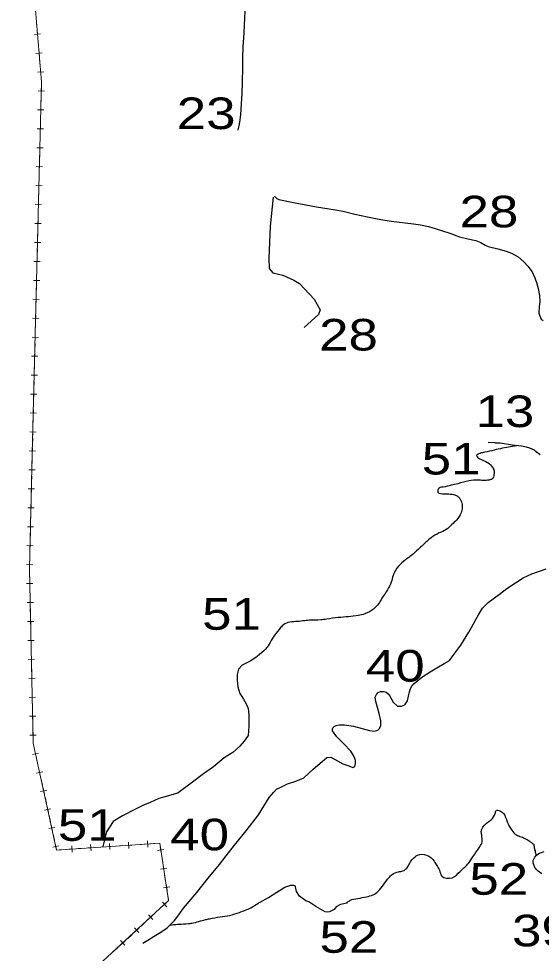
# Model space of a CAD drawing. Extents: x 476989 to 498418, y 4381813 to 4416555.
# Drawn here: x 483851 to 484677, y 4385658 to 4387137 of the extents above; entities that cross this region are included whole.
import ezdxf
from ezdxf.enums import TextEntityAlignment as Align

# ---------------------------------------------------------------- set-up
doc = ezdxf.new("R2010")
doc.units = 0
doc.header["$LTSCALE"] = 20
for name, color, linetype, lineweight in [('13', 7, 'Continuous', 13), ('34', 7, 'Continuous', 13), ('6', 7, 'Continuous', 25)]:
    doc.layers.add(name, color=color, linetype=linetype, lineweight=lineweight)

msp = doc.modelspace()

# ---------------------------------------------------------------- linework, layer by layer
at = {"layer": '34'}
for p, q in [((483879.05, 4387132.21), (483879.88, 4387122.24)), ((483875.73, 4387111.86), (483885.7, 4387112.69)), ((483880.3, 4387117.26), (483881.13, 4387107.29)), ((483881.54, 4387102.31), (483882.38, 4387092.35)), ((483878.23, 4387081.96), (483888.19, 4387082.8)), ((483882.79, 4387087.36), (483883.63, 4387077.4)), ((483884.04, 4387072.41), (483884.87, 4387062.45)), ((483880.72, 4387052.07), (483890.69, 4387052.9)), ((483885.29, 4387057.47), (483886.12, 4387047.5)), ((483881.65, 4387022.67), (483891.64, 4387022.42)), ((483886.77, 4387027.54), (483886.52, 4387017.54)), ((483886.4, 4387012.55), (483886.15, 4387002.55)), ((483880.91, 4386992.67), (483890.9, 4386992.43)), ((483886.03, 4386997.55), (483885.78, 4386987.55)), ((483885.66, 4386982.55), (483885.41, 4386972.56)), ((483880.17, 4386962.68), (483890.16, 4386962.44)), ((483885.29, 4386967.56), (483885.04, 4386957.56)), ((483884.92, 4386952.56), (483884.67, 4386942.57)), ((483879.43, 4386932.69), (483889.42, 4386932.45)), ((483884.55, 4386937.57), (483884.3, 4386927.57)), ((483884.18, 4386922.57), (483883.93, 4386912.58)), ((483878.69, 4386902.7), (483888.69, 4386902.46)), ((483883.81, 4386907.58), (483883.56, 4386897.58)), ((483883.44, 4386892.58), (483883.19, 4386882.58)), ((483877.95, 4386872.71), (483887.95, 4386872.46)), ((483883.07, 4386877.59), (483882.83, 4386867.59)), ((483882.7, 4386862.59), (483882.46, 4386852.59)), ((483877.21, 4386842.72), (483887.21, 4386842.47)), ((483882.33, 4386847.6), (483882.09, 4386837.6)), ((483881.96, 4386832.6), (483881.72, 4386822.6)), ((483876.47, 4386812.73), (483886.47, 4386812.48)), ((483881.59, 4386817.6), (483881.35, 4386807.61)), ((483881.22, 4386802.61), (483880.98, 4386792.61)), ((483875.73, 4386782.74), (483885.73, 4386782.49)), ((483880.85, 4386787.61), (483880.61, 4386777.62)), ((483880.48, 4386772.62), (483880.24, 4386762.62)), ((483874.99, 4386752.75), (483884.99, 4386752.5)), ((483880.12, 4386757.62), (483879.87, 4386747.63)), ((483879.75, 4386742.63), (483879.5, 4386732.63)), ((483874.25, 4386722.76), (483884.25, 4386722.51)), ((483879.38, 4386727.63), (483879.13, 4386717.64)), ((483879.01, 4386712.64), (483878.76, 4386702.64)), ((483878.64, 4386697.64), (483878.39, 4386687.64)), ((483873.52, 4386692.77), (483883.51, 4386692.52)), ((483878.27, 4386682.65), (483878.02, 4386672.65)), ((483877.9, 4386667.65), (483877.65, 4386657.65)), ((483872.78, 4386662.77), (483882.77, 4386662.53)), ((483877.53, 4386652.65), (483877.28, 4386642.66)), ((483877.16, 4386637.66), (483876.91, 4386627.66)), ((483872.04, 4386632.78), (483882.03, 4386632.54)), ((483876.79, 4386622.66), (483876.54, 4386612.67)), ((483876.42, 4386607.67), (483876.17, 4386597.67)), ((483871.3, 4386602.79), (483881.3, 4386602.55)), ((483876.05, 4386592.67), (483875.8, 4386582.68)), ((483875.68, 4386577.68), (483875.43, 4386567.68)), ((483870.56, 4386572.8), (483880.56, 4386572.56)), ((483875.31, 4386562.68), (483875.06, 4386552.69)), ((483874.94, 4386547.69), (483874.7, 4386537.69)), ((483869.82, 4386542.81), (483879.82, 4386542.56)), ((483874.57, 4386532.69), (483874.33, 4386522.69)), ((483874.2, 4386517.7), (483873.96, 4386507.7)), ((483869.08, 4386512.82), (483879.08, 4386512.57)), ((483873.83, 4386502.7), (483873.59, 4386492.7)), ((483873.46, 4386487.7), (483873.22, 4386477.71)), ((483868.34, 4386482.83), (483878.34, 4386482.58)), ((483873.09, 4386472.71), (483872.85, 4386462.71)), ((483872.72, 4386457.71), (483872.5, 4386448.65)), ((483867.6, 4386452.84), (483877.6, 4386452.59)), ((483872.35, 4386442.72), (483872.11, 4386432.72)), ((483872.5, 4386448.65), (483872.48, 4386447.72)), ((483871.99, 4386427.72), (483871.74, 4386417.73)), ((483866.86, 4386422.85), (483876.86, 4386422.6)), ((483871.62, 4386412.73), (483871.37, 4386402.73)), ((483871.25, 4386397.73), (483871, 4386387.74)), ((483866.12, 4386392.86), (483876.12, 4386392.61)), ((483870.88, 4386382.74), (483870.63, 4386372.74)), ((483870.51, 4386367.74), (483870.26, 4386357.74)), ((483865.39, 4386362.87), (483875.38, 4386362.62)), ((483870.14, 4386352.75), (483869.89, 4386342.75)), ((483864.65, 4386332.88), (483874.64, 4386332.63)), ((483869.77, 4386337.75), (483869.52, 4386327.75)), ((483869.4, 4386322.75), (483869.15, 4386312.76)), ((483863.91, 4386302.88), (483873.9, 4386302.64)), ((483869.03, 4386307.76), (483868.78, 4386297.76)), ((483868.66, 4386292.76), (483868.41, 4386282.77)), ((483863.17, 4386272.89), (483873.17, 4386272.65)), ((483868.29, 4386277.77), (483868.04, 4386267.77)), ((483868.07, 4386262.77), (483868.29, 4386252.78)), ((483863.51, 4386242.67), (483873.5, 4386242.89)), ((483868.4, 4386247.78), (483868.61, 4386237.78)), ((483868.72, 4386232.78), (483868.94, 4386222.78)), ((483864.16, 4386212.68), (483874.16, 4386212.89)), ((483869.05, 4386217.78), (483869.27, 4386207.79)), ((483869.37, 4386202.79), (483869.59, 4386192.79)), ((483864.81, 4386182.68), (483874.81, 4386182.9)), ((483869.7, 4386187.79), (483869.92, 4386177.79)), ((483870.03, 4386172.79), (483870.24, 4386162.8)), ((483865.46, 4386152.69), (483875.46, 4386152.91)), ((483870.35, 4386157.8), (483870.57, 4386147.8)), ((483870.68, 4386142.8), (483870.9, 4386132.8)), ((483866.11, 4386122.7), (483876.11, 4386122.91)), ((483871, 4386127.8), (483871.22, 4386117.81)), ((483871.33, 4386112.81), (483871.55, 4386102.81)), ((483866.77, 4386092.7), (483876.76, 4386092.92)), ((483871.66, 4386097.81), (483871.87, 4386087.81)), ((483871.98, 4386082.82), (483872.2, 4386072.82)), ((483867.42, 4386062.71), (483877.42, 4386062.93)), ((483872.31, 4386067.82), (483872.53, 4386057.82)), ((483872.63, 4386052.82), (483872.85, 4386042.82)), ((483868.07, 4386032.72), (483878.07, 4386032.94)), ((483872.96, 4386037.83), (483873.18, 4386027.83)), ((483873.29, 4386022.83), (483873.5, 4386012.83)), ((483868.72, 4386002.73), (483878.72, 4386002.94)), ((483873.61, 4386007.83), (483873.83, 4385997.84)), ((483872.79, 4385972.17), (483882.55, 4385974.3)), ((483876.6, 4385978.12), (483878.74, 4385968.35)), ((483879.81, 4385963.47), (483881.95, 4385953.7)), ((483879.2, 4385942.86), (483888.97, 4385945)), ((483883.02, 4385948.81), (483885.16, 4385939.04)), ((483886.23, 4385934.16), (483888.36, 4385924.39)), ((483885.62, 4385913.55), (483895.39, 4385915.69)), ((483889.43, 4385919.51), (483891.57, 4385909.74)), ((483892.64, 4385904.85), (483894.78, 4385895.09)), ((483892.03, 4385884.25), (483901.8, 4385886.39)), ((483895.85, 4385890.2), (483897.99, 4385880.43)), ((483899.06, 4385875.55), (483901.2, 4385865.78)), ((483898.45, 4385854.94), (483908.22, 4385857.08)), ((483902.27, 4385860.9), (483904.4, 4385851.13)), ((483905.47, 4385846.24), (483907.61, 4385836.47)), ((484055.17, 4385825.72), (484054.5, 4385835.7)), ((483904.87, 4385825.64), (483914.64, 4385827.77)), ((483908.68, 4385831.59), (483910.82, 4385821.82)), ((483915.15, 4385821.28), (483925.13, 4385821.95)), ((483930.12, 4385822.29), (483940.09, 4385822.96)), ((483935.44, 4385817.64), (483934.77, 4385827.62)), ((483945.08, 4385823.3), (483955.06, 4385823.97)), ((483960.05, 4385824.31), (483970.03, 4385824.98)), ((483965.37, 4385819.66), (483964.7, 4385829.64)), ((483975.01, 4385825.32), (483984.99, 4385825.99)), ((483989.98, 4385826.33), (483999.96, 4385827)), ((483995.31, 4385821.68), (483994.63, 4385831.66)), ((484004.95, 4385827.34), (484014.92, 4385828.01)), ((484019.91, 4385828.35), (484029.89, 4385829.02)), ((484025.24, 4385823.7), (484024.56, 4385833.68)), ((484034.88, 4385829.36), (484044.86, 4385830.03)), ((484049.84, 4385830.37), (484059.82, 4385831.04)), ((484070.7, 4385820.58), (484080.58, 4385822.1)), ((484074.88, 4385826.28), (484076.4, 4385816.39)), ((484077.16, 4385811.45), (484078.68, 4385801.57)), ((484075.26, 4385790.93), (484085.14, 4385792.45)), ((484079.44, 4385796.63), (484080.96, 4385786.74)), ((484081.72, 4385781.8), (484083.24, 4385771.92)), ((484079.82, 4385761.27), (484089.71, 4385762.79)), ((484084, 4385766.98), (484085.52, 4385757.09)), ((484086.28, 4385752.15), (484087.81, 4385742.27)), ((484085.27, 4385738.48), (484077.93, 4385731.69)), ((484078.2, 4385738.75), (484084.99, 4385731.41)), ((484063.24, 4385718.11), (484055.9, 4385711.32)), ((484056.18, 4385718.38), (484062.97, 4385711.04)), ((484074.26, 4385728.29), (484066.92, 4385721.5)), ((484052.23, 4385707.92), (484044.89, 4385701.13)), ((484030.21, 4385687.56), (484022.86, 4385680.77)), ((484041.22, 4385697.74), (484033.88, 4385690.95)), ((484034.15, 4385698.02), (484040.94, 4385690.67)), ((484019.19, 4385677.37), (484011.85, 4385670.58)), ((484012.13, 4385677.65), (484018.92, 4385670.31)), ((484008.18, 4385667.19), (484000.84, 4385660.4))]:
    msp.add_line(p, q, dxfattribs=at)
for points in [[(484108, 4387807), (483853, 4387811), (483851, 4387468), (483887, 4387037), (483872.5, 4386448.65)], [(483886.54, 4387042.52), (483887, 4387037), (483886.89, 4387032.54)], [(483872.5, 4386448.65), (483868, 4386266), (483874, 4385990), (483911, 4385821), (484074, 4385832), (484088, 4385741), (483902, 4385569), (484007, 4385465), (484103, 4385395), (484103.22, 4385394.84)], [(483873.94, 4385992.84), (483874, 4385990), (483875.53, 4385983)], [(484064.81, 4385831.38), (484074, 4385832), (484074.12, 4385831.22)]]:
    msp.add_lwpolyline(points, dxfattribs=at)
at = {"layer": '6'}
msp.add_line((484669.78, 4386451.55), (484675.59, 4386447), dxfattribs=at)
for points in [[(484212.82, 4387295.28), (484212.47, 4387278.4), (484211.44, 4387240.58), (484210.65, 4387220.54), (484209.3, 4387209.89), (484208.08, 4387198.84), (484207.98, 4387189.84), (484208.12, 4387179.31), (484208.42, 4387167.67), (484208.7, 4387158.03), (484208.44, 4387149.25), (484207.87, 4387137.58), (484207.04, 4387114.72), (484205.45, 4387091.7), (484204.57, 4387075.39), (484204.95, 4387059.47), (484204.36, 4387036.27), (484203.86, 4387018.17), (484202.77, 4387002.21), (484201.65, 4386984.79), (484200.05, 4386972.86), (484199.05, 4386967.22), (484197.58, 4386960.92), (484197.42, 4386960.48)], [(484255.26, 4386856.24), (484255.51, 4386855.85), (484259.2, 4386852.12), (484262.08, 4386850.81), (484285.37, 4386846.1), (484321.78, 4386839.14), (484351.99, 4386834.18), (484364.12, 4386832.42), (484382.29, 4386827.59), (484402.33, 4386823.45), (484423.29, 4386819.3), (484439.77, 4386816.4), (484475.05, 4386811.94), (484486.31, 4386810.65), (484498.67, 4386808.05), (484509.39, 4386804.9), (484532.44, 4386797.25), (484547.84, 4386791.37), (484560.89, 4386788.41), (484573.56, 4386785.73), (484581.82, 4386782.58), (484588.73, 4386778.34), (484593.26, 4386776.54), (484608.53, 4386772.83), (484621.89, 4386768.75), (484629.95, 4386765.83), (484640.85, 4386759.96), (484649.61, 4386752.18), (484656.1, 4386745.44), (484662.74, 4386736.14), (484667.21, 4386726.6), (484670.12, 4386717.75), (484672.45, 4386709.7), (484674.51, 4386698.8), (484674.86, 4386688.69), (484673.94, 4386681.56), (484673.61, 4386671.01), (484674.2, 4386667.61), (484677.03, 4386661.52), (484680.13, 4386659.31)], [(484253.58, 4386854.18), (484248.8, 4386808.66), (484246.41, 4386757.54), (484247.21, 4386741.57), (484252.78, 4386734.38), (484268.71, 4386731.19), (484286.22, 4386723.2), (484294.98, 4386717.61), (484318.07, 4386692.85), (484327.62, 4386676.08), (484325.23, 4386668.89), (484302.14, 4386648.12)], [(484593.43, 4386466.83), (484593.45, 4386466.82), (484603.22, 4386466), (484604.19, 4386465.78), (484612, 4386465.4), (484631.54, 4386462.29), (484646.09, 4386460.77), (484653.53, 4386459.28), (484658.44, 4386457.47), (484658.41, 4386457.42), (484665.79, 4386454.57), (484669.78, 4386451.55)], [(484379.37, 4385951.8), (484382.66, 4385953.41), (484383.69, 4385958.07), (484383.38, 4385962.64), (484382.38, 4385966.13), (484380.36, 4385970.61), (484376.08, 4385977.48), (484365.25, 4385989.07), (484353.82, 4386000.13), (484347.19, 4386009.82), (484347.05, 4386012.71), (484347.75, 4386014.63), (484350.02, 4386016.52), (484352.81, 4386018.1), (484357.54, 4386019.26), (484364.31, 4386019.32), (484365.47, 4386019.23), (484380.1, 4386017.06), (484394.06, 4386013.66), (484405.63, 4386010.39), (484412.36, 4386009.4), (484418.84, 4386010.62), (484421.41, 4386013.67), (484423.43, 4386018.43), (484423.38, 4386025.55), (484421.08, 4386037.22), (484415.43, 4386056.06), (484414.66, 4386063.2), (484416.5, 4386067.21), (484419.08, 4386070.17), (484423.1, 4386072.23), (484428.44, 4386071.87), (484432.24, 4386070.97), (484435.37, 4386068.48), (484437.13, 4386065.76), (484442.92, 4386055.26), (484450.13, 4386048.79), (484456.05, 4386048.77), (484461.7, 4386051.08), (484465.57, 4386057.36), (484467.35, 4386064.5), (484468.65, 4386071.5), (484470.33, 4386076.74), (484472.67, 4386080.51), (484476.1, 4386084.8), (484488.44, 4386094.73), (484501.37, 4386103.34), (484514.77, 4386111.11), (484523.77, 4386116.07), (484532.01, 4386121.17), (484540.68, 4386132.52), (484549.93, 4386145.08), (484562.6, 4386165.73), (484567.13, 4386173.42), (484573.89, 4386186.16), (484577.92, 4386193.43), (484584.11, 4386203.94), (484593.25, 4386212.62), (484611.2, 4386226.27), (484622.57, 4386235.08), (484636.27, 4386244.07), (484648.45, 4386251.66), (484662.04, 4386258.08), (484685.19, 4386265.93)], [(484239.1, 4386136.78), (484227.91, 4386127.44), (484218.03, 4386120.66), (484204.44, 4386113.88), (484198.27, 4386107.09), (484196.42, 4386099.08), (484196.42, 4386089.83), (484197.65, 4386079.35), (484200.74, 4386068.86), (484202.69, 4386065.47), (484206.59, 4386059.6)], [(484206.44, 4386060.05), (484210.6, 4386052.54), (484213.69, 4386045.14), (484214.93, 4386035.26), (484214.93, 4386025.39), (484214.93, 4386017.37), (484213.69, 4386002.56), (484207.51, 4385993.3), (484200.72, 4385985.28), (484189.6, 4385975.41), (484176.02, 4385966.77), (484158.73, 4385952.57), (484143.29, 4385941.47), (484125.99, 4385928.51), (484103.14, 4385911.85)], [(484103.92, 4385718.57), (484111.72, 4385728.95), (484132.39, 4385753.72), (484150.74, 4385776.42), (484168.25, 4385798.21), (484178.85, 4385811.99), (484192.12, 4385829), (484210.84, 4385851.58), (484229.9, 4385876.92), (484247.2, 4385904.12), (484254.19, 4385912.82), (484258.83, 4385917.22), (484264.2, 4385920.12), (484276.08, 4385925.76), (484289.25, 4385930.22), (484301.63, 4385935.61), (484316.4, 4385948.98), (484330.76, 4385961.22)], [(484330.76, 4385961.22), (484338.28, 4385967.32), (484344.45, 4385967.94), (484354.95, 4385962.38), (484363.6, 4385957.45), (484372.86, 4385954.36), (484379.37, 4385951.8)], [(484103.55, 4385911.73), (484091.43, 4385907.86), (484072.53, 4385902.53), (484058.95, 4385896.24), (484047.32, 4385891.4), (484035.69, 4385885.59), (484014.85, 4385874.95), (484000.3, 4385866.24), (483989.64, 4385849.78), (483983.82, 4385826.55)], [(484677.94, 4385783.18), (484672.46, 4385787.45), (484670.1, 4385789.86), (484667.17, 4385793.46), (484664.19, 4385800.81), (484664.55, 4385804.26), (484667.17, 4385809.62), (484670.46, 4385813.3), (484674.66, 4385816.15), (484681.59, 4385818.87)], [(484232.71, 4385738.67), (484245.82, 4385746.08), (484258.89, 4385754.17), (484271.96, 4385762.25), (484281.3, 4385765.36), (484285.65, 4385765.36), (484288.73, 4385763.8)], [(484369.87, 4385737.2), (484364.99, 4385736.16), (484360, 4385734.88), (484353.19, 4385731.05), (484349.68, 4385726.82), (484342.51, 4385723.3), (484339.54, 4385722.65), (484335.38, 4385723.47), (484320.6, 4385731.82), (484309.66, 4385739), (484305.07, 4385740.5), (484294.96, 4385748), (484290.13, 4385755.39), (484288.41, 4385763.09), (484288.39, 4385763.58)], [(484047.21, 4385673.91), (484055.33, 4385678.48), (484065.21, 4385684.94), (484075.49, 4385691.28), (484085.83, 4385698.04), (484090.13, 4385702.27), (484097.28, 4385709.73), (484103.92, 4385718.57)]]:
    msp.add_lwpolyline(points, dxfattribs=at)
for points in [[(484641.08, 4386461.3), (484615.93, 4386456.98), (484602.56, 4386454.05), (484588.02, 4386450.63), (484580.56, 4386448.95), (484576.61, 4386447.19)], [(484576.61, 4386447.19), (484575.13, 4386446.53), (484575.18, 4386444.85), (484580.13, 4386440.31), (484591.1, 4386435.01), (484598.73, 4386428.86), (484602.1, 4386423.08), (484602.37, 4386415.22), (484599.42, 4386408.45), (484594.78, 4386406.63), (484585.36, 4386406.05), (484576.72, 4386406.48), (484563.21, 4386405.29), (484545.28, 4386400.82), (484534.96, 4386398.38), (484521.91, 4386395.52), (484514.17, 4386392.31), (484513.85, 4386387.73), (484523.95, 4386384.82), (484528.86, 4386384.69), (484538.58, 4386383.69), (484545.75, 4386380.25), (484548.92, 4386376.43), (484552.06, 4386367.9), (484551.7, 4386358.89), (484550.52, 4386355.02), (484543.31, 4386343.35), (484535.9, 4386336.43), (484527.04, 4386328.4), (484515.84, 4386322.97), (484502.88, 4386315.06), (484490.08, 4386303.77), (484482.61, 4386296.93), (484472.42, 4386287.91), (484462.75, 4386280.64), (484451.72, 4386270.36), (484442.91, 4386255.77), (484439.95, 4386245.25), (484434.08, 4386232.96), (484425.31, 4386219.46), (484419.84, 4386210.8), (484412.03, 4386202.36), (484398.36, 4386194.84), (484387.5, 4386192.19), (484372.49, 4386190.28), (484356.35, 4386188.98), (484338.03, 4386186.55), (484328.45, 4386185.35), (484310.94, 4386184.71), (484289, 4386182.56), (484276.75, 4386181.11), (484267.68, 4386175.87), (484262.62, 4386170.12), (484253.51, 4386158.01), (484247.07, 4386147.03), (484239.03, 4386136.69)], [(484369.69, 4385737.23), (484374.57, 4385741.25), (484387.05, 4385744.42), (484401.1, 4385747.22), (484411.47, 4385750.14), (484418.64, 4385755.36), (484427.98, 4385766.15), (484436.47, 4385777.61), (484441.49, 4385782.4), (484451.37, 4385786.51), (484458.52, 4385788.13), (484464.47, 4385792.51), (484468.73, 4385799.27), (484477.71, 4385810.44), (484481.55, 4385812.74), (484495.71, 4385813.19), (484507.73, 4385803.27), (484511.98, 4385796.51), (484516.11, 4385789.27), (484519.94, 4385779.82), (484536.29, 4385777.31), (484548.82, 4385787.09), (484560.77, 4385798.6), (484569.09, 4385810.32), (484574.95, 4385818.97), (484583.57, 4385833.88), (484582.99, 4385844.94), (484582.37, 4385850.18), (484590.45, 4385863.44), (484598.39, 4385869.16), (484604.27, 4385879.03), (484606.52, 4385884.01), (484610.62, 4385883.7), (484617.41, 4385878.95), (484623.48, 4385865.81), (484630.54, 4385852.41), (484637.92, 4385844.92), (484645.47, 4385842.02), (484653.1, 4385838.51), (484656.48, 4385836.87), (484663.31, 4385831.44), (484664.35, 4385830.75), (484665.94, 4385824.73), (484667.79, 4385817.91), (484668.54, 4385814.07), (484669.03, 4385811.7)], [(484103.89, 4385703.63), (484119.2, 4385704.68), (484124.8, 4385705.49), (484146.59, 4385710.97), (484152.48, 4385712.37), (484169.37, 4385715.15), (484184.78, 4385717.66), (484200.05, 4385722.45), (484218.09, 4385729.84), (484229.06, 4385736.5), (484233.74, 4385739.28)], [(484090.86, 4385702.36), (484101.98, 4385703.5), (484103.89, 4385703.63)]]:
    msp.add_spline(points, degree=3, dxfattribs=at)

# ---------------------------------------------------------------- texts
at = {"layer": '13', "width": 1.25}
for s, p in [('23', (484147.37, 4386962.13)), ('28', (484594.48, 4386806.61)), ('28', (484372.43, 4386611.69)), ('13', (484619.71, 4386490.5)), ('51', (484534.7, 4386415.46)), ('51', (484187.42, 4386169.73)), ('40', (484446.34, 4386087.68)), ('51', (483959.38, 4385835.64)), ('40', (484137.13, 4385820.61)), ('52', (484610.04, 4385750.33)), ('39', (484677.48, 4385668.68)), ('52', (484373, 4385658.47))]:
    msp.add_text(s, height=50, dxfattribs=at).set_placement(p, align=Align.CENTER)

doc.saveas('drawing.dxf')
